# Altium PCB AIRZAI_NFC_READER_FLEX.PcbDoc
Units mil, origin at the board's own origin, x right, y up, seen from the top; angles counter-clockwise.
Board outline 3488.72 x 5808.52 mil, 2 copper layers (Top Layer, Bottom Layer); 39 components, 43 nets, 190 pads, 9 vias.
Unrouted connection lines stored in the file: 129.
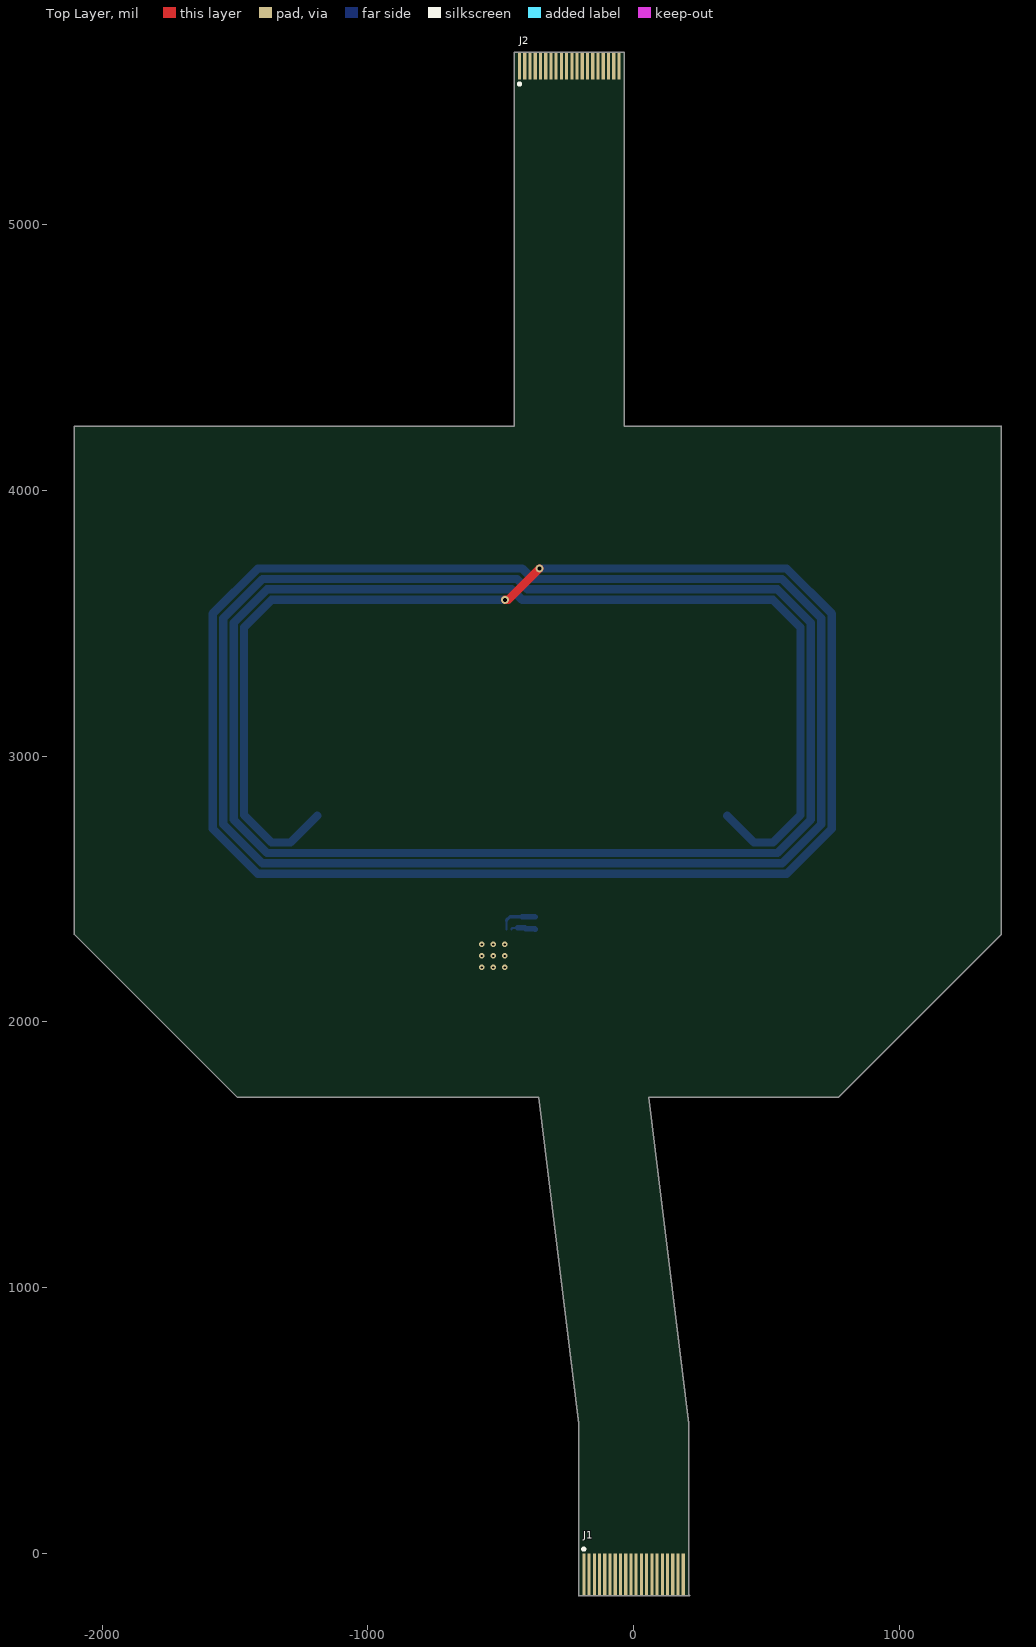
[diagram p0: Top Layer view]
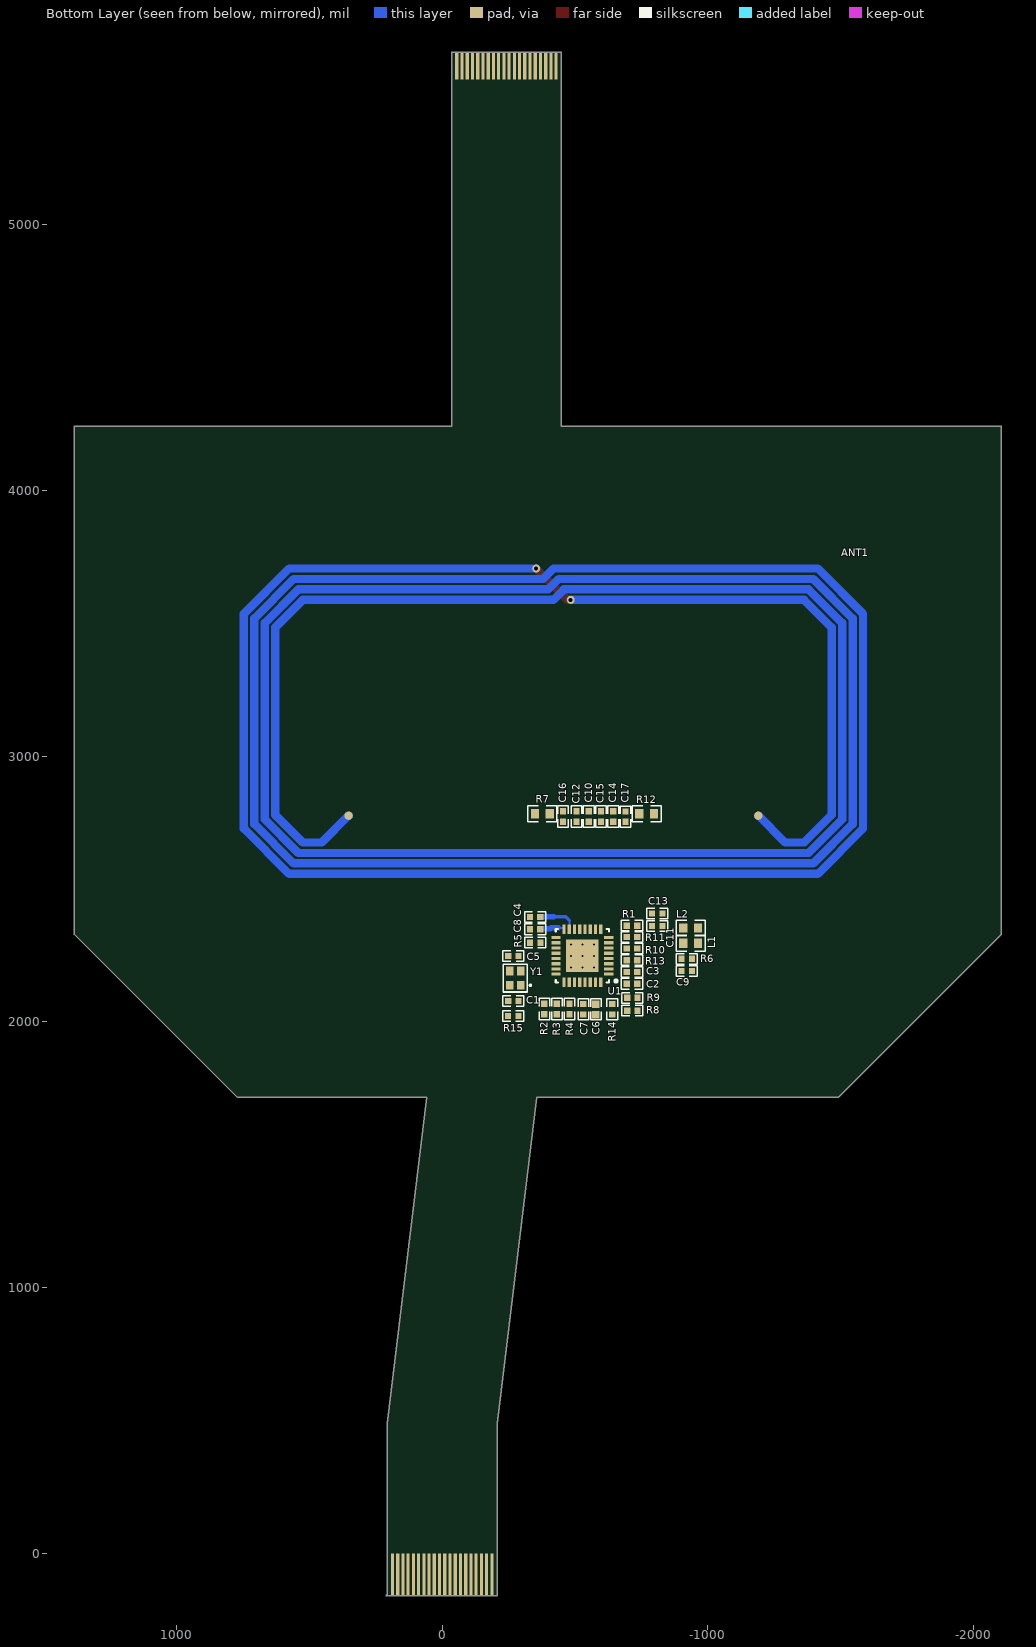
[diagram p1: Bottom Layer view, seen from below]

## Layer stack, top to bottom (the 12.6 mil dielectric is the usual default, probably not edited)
Top Solder: solder mask 0.4, Solder Resist, Dk 3.5
Top Layer: signal copper 1.4
Dielectric 1: dielectric 12.6, FR-4, Dk 4.8
Bottom Layer: signal copper 1.4
Bottom Solder: solder mask 0.4, Solder Resist, Dk 3.5

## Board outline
-1490.79,1715.7 -356.15,1715.7 -206.96,488.48 -206.96,488.46 -206.96,488.48 -206.96,-159.02 ccw(c-206.69,-159.02) -206.69,-159.28 210.63,-159.28 ccw(c210.63,-159.02) 210.89,-159.02 ccw(c210.63,-159.02) 210.63,-158.75 206.96,-158.75 206.96,488.49 ccw(c206.69,488.49) 206.96,488.53 57.77,1715.7 770.31,1715.7 ccw(c770.31,1715.96) 770.5,1715.77 1384.05,2329.32 ccw(c1383.86,2329.5) 1384.12,2329.5 1384.12,2490.96 1384.12,4242.28 ccw(c1383.86,4242.28) 1383.86,4242.55 -35.17,4242.55 -35.17,5648.98 ccw(c-35.43,5648.98) -35.43,5649.24 -448.82,5649.24 ccw(c-448.82,5648.98) -449.08,5648.98 -449.08,4242.55 -2104.33,4242.55 ccw(c-2104.33,4242.28) -2104.6,4242.28 -2104.6,2490.96 -2104.6,2329.5 ccw(c-2104.33,2329.5) -2104.52,2329.32 -1490.97,1715.77 ccw(c-1490.79,1715.96)

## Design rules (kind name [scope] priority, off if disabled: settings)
Clearance Clearance_polygon_5V [OnLayer('Keep-Out Layer') vs (InNet('+5V') AND InPolygon)] p1: gap=10 ignorepadtopadclearanceinfootprint=FALSE
Clearance Clearance_POLYGON_KEEPOUT [(OnLayer('Keep-Out Layer')) vs (InNet('GND') AND InPolygon)] p2: gap=10 ignorepadtopadclearanceinfootprint=FALSE
Clearance [All] p3: gap=6 ignorepadtopadclearanceinfootprint=FALSE
MinimumSolderMaskSliver [All] p1: minsoldermaskwidth=1
PolygonConnect [All] p1: connectstyle=Direct reliefconductorwidth=10 reliefentries=4 polygonreliefangle="90 Angle" airgapwidth=10
RoomDefinition AIRZAI_NFC_READER_FLEX [InComponentClass('AIRZAI_NFC_READER_FLEX')] p1: confinementstyle=ConfineIn formatcopy=TRUE lockcomponents=FALSE outline -17244.57,-12935.21 -2584.57,-12935.21 -2584.57,-3335.21 -17244.57,-3335.21
RoutingVias [All] p1: holewidth=28 width=50 viastyle="Through Hole" minholewidth=8 minwidth=16 maxholewidth=28 maxwidth=50
SilkToSilkClearance [All] p1: silktosilkclearance=1
SilkToSolderMaskClearance [IsPad] p1: minsilkscreentomaskgap=2 clearancetoexposedcopper=TRUE
SolderMaskExpansion [All] p1: expansion=4
UnRoutedNet [All] p1: checkbadconnections=TRUE
Width [All] p1: maxlimit=100 minlimit=6 preferedwidth=10
26 further rules are at their usual default settings.

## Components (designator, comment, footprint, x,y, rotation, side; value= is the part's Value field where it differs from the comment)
ANT1 "NFC_ANT" ANTENNA-NFC-60MMX30MM -419,3132 r0 bottom
C1 "12pF" 0402CAP -267.98,2078.44 r180 bottom
C2 "0.1µF" 0402CAP -714.98,2143.57 r180 bottom
C3 "0.1µF" 0402CAP -714.98,2188.25 r180 bottom
C4 "0.1µF" 0402CAP -349.98,2394.76 r0 bottom
C5 "12pF" 0402CAP -267.98,2248.44 r0 bottom
C6 "1uF" CAPC0402(1005)60_M -578.42,2047.44 r90 bottom
C7 "0.1µF" 0402CAP -531.42,2047.44 r270 bottom
C8 "0.1µF" 0402CAP -349.98,2348.76 r0 bottom
C9 "1nF" 0402CAP -920.37,2191.44 r0 bottom
C10 "18pF" 0402CAP -552,2773 r270 bottom
C11 "220pF" 0402CAP -809.29,2361.22 r180 bottom
C12 "47pF" 0402CAP -506,2773 r90 bottom
C13 "220pF" 0402CAP -809.29,2408.22 r0 bottom
C14 "47pF" 0402CAP -644,2773 r270 bottom
C15 "18pF" 0402CAP -598,2773 r270 bottom
C16 "DNP" 0402CAP -454.44,2773 r90 bottom
C17 "DNP" 0402CAP -690,2772.69 r270 bottom
J1 "FFC Cable" FFC_PADS_MBD -9.84,-80.28 r180 top
J2 "FFC Cable" FFC_PADS_LID -251.97,5597.8 r180 top
L1 "560nH" 0603CAP -935.37,2295.44 r0 bottom
L2 "560mH" 0603CAP -935.37,2353.44 r0 bottom
R1 "0R" 0402 -714.79,2362.44 r180 bottom
R2 "10K" 0402 -384.68,2048.44 r90 bottom
R3 "10K" 0402 -431.68,2048.44 r90 bottom
R4 "10K" 0402 -479.42,2048.44 r90 bottom
R5 "1K" 0402 -350.23,2298.44 r180 bottom
R6 "2.7K" 0402 -920.69,2237.44 r180 bottom
R7 "3.3" 0603 -377,2783 r180 bottom
R8 "10K" 0402 -715.98,2042.44 r180 bottom
R9 "10K" 0402 -715.98,2090.44 r180 bottom
R10 "0R" 0402 -714.98,2276.44 r180 bottom
R11 "0R" 0402 -714.79,2319.44 r180 bottom
R12 "3.3" 0603 -770,2783 r0 bottom
R13 "10K" 0402 -714.79,2232.44 r180 bottom
R14 "0R" 0402 -640.42,2047.44 r270 bottom
R15 "0R" 0402 -267.31,2022.44 r0 bottom
U1 "MFRC52202HN1,115" VFQFN-32-MFRC52202HN1,157 -527.98,2248.76 r0 bottom
Y1 "27.12MHz" XTAL_2016 -274.98,2164.44 r90 bottom

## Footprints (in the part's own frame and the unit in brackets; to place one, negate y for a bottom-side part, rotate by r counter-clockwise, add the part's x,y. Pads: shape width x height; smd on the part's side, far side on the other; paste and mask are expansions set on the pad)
0402 [mm] "Chip Resistor, Body 1.1x0.5mm, IPC High Density"
  rect 0.6x0.6 smd: 1(-0.5,0) 2(0.5,0)
  silkscreen extent -1.02,-0.51 1.02,0.51, body extent -0.5,-0.25 0.5,0.25, height 0.27
0402CAP [mm] "Chip Capacitor, Body 1.1x0.5mm, IPC High Density"
  rect 0.6x0.6 smd: 1(-0.5,0) 2(0.5,0)
  silkscreen extent -1.02,-0.51 1.02,0.51, body extent -0.5,-0.3 0.5,0.3, height 0.19
0603 [mm] "Chip Resistor, Body 1.6x0.8mm, IPC High Density"
  rect 0.8x0.9 smd: 1(-0.7,0) 2(0.7,0)
  silkscreen extent -1.4,-0.76 1.4,0.76, body extent -0.8,-0.41 0.8,0.4, height 0.37
0603CAP [mm] "Chip Capacitor, Body 1.6x0.8mm, IPC High Density"
  rect 0.8x0.9 smd: 1(-0.7,0) 2(0.7,0)
  silkscreen extent -1.4,-0.76 1.4,0.76, body extent -0.8,-0.4 0.8,0.4, height 0.29
ANTENNA-NFC-60MMX30MM [mil] "ANTENNA-ID2+10P-01"
  round 31.5 smd paste-31.5: 1(-771.2,355.65) 2(771.2,355.65)
  round 30 hole 15: 1(-65,-456.69) 2(65,-574.8)
  Top Layer lines w31.5: -771.2,355.65 -872.24,456.69 -943.7,456.69 -1047.24,353.15 -1047.24,-353.15 -943.7,-456.69 -65,-456.69 ; 65,-574.8 994.96,-574.8 1165.35,-404.41 1165.35,404.41 994.96,574.8 -994.96,574.8 -1165.35,404.41 -1165.35,-404.41 -994.96,-574.8 0,-574.8 39.37,-535.43 977.87,-535.43 1125.98,-387.32 1125.98,387.32 977.87,535.43 -977.87,535.43 -1125.98,387.32 -1125.98,-387.32 -977.87,-535.43 -19.37,-535.43 20,-496.06 960.79,-496.06 1086.61,-370.24 1086.61,370.24 960.79,496.06 -960.79,496.06 -1086.61,370.24 -1086.61,-370.24 -960.79,-496.06 -39.37,-496.06 0,-456.69 943.7,-456.69 1047.24,-353.15 1047.24,353.15 943.7,456.69 872.24,456.69 771.2,355.65
  Bottom Layer lines w31.5: -65,-456.69 -53.11,-456.69 65,-574.8
CAPC0402(1005)60_M [mm] "Chip Capacitor, Body 1.0x0.5mm, Height 0.6mm, IPC Low Density"
  rect 0.72x0.72 smd: 1(-0.5,0) 2(0.5,0)
  silkscreen extent -1.02,-0.51 1.02,0.51, body extent -0.55,-0.3 0.55,0.3, height 0.6
FFC_PADS_LID [mm] "(0.50mm"
  rect 0.3x2.6 smd: 1(4.5,0) 2(4,0) 3(3.5,0) 4(3,0) 5(2.5,0) 6(2,0) 7(1.5,0) 8(1,0) 9(0.5,0) 10(0,0) 11(-0.5,0) 12(-1,0) 13(-1.5,0) 14(-2,0) 15(-2.5,0) 16(-3,0) 17(-3.5,0) 18(-4,0) 19(-4.5,0) 20(-5,0)
  rect 0.3x2.6 smd far side: 1(4.5,0) 2(4,0) 3(3.5,0) 4(3,0) 5(2.5,0) 6(2,0) 7(1.5,0) 8(1,0) 9(0.5,0) 10(0,0) 11(-0.5,0) 12(-1,0) 13(-1.5,0) 14(-2,0) 15(-2.5,0) 16(-3,0) 17(-3.5,0) 18(-4,0) 19(-4.5,0) 20(-5,0)
  silkscreen extent 4.37,1.58 4.62,1.83
FFC_PADS_MBD [mm] "(0.50mm"
  rect 0.3x4 smd: 1(4.5,0) 2(4,0) 3(3.5,0) 4(3,0) 5(2.5,0) 6(2,0) 7(1.5,0) 8(1,0) 9(0.5,0) 10(0,0) 11(-0.5,0) 12(-1,0) 13(-1.5,0) 14(-2,0) 15(-2.5,0) 16(-3,0) 17(-3.5,0) 18(-4,0) 19(-4.5,0) 20(-5,0)
  rect 0.3x4 smd far side: 1(4.5,0) 2(4,0) 3(3.5,0) 4(3,0) 5(2.5,0) 6(2,0) 7(1.5,0) 8(1,0) 9(0.5,0) 10(0,0) 11(-0.5,0) 12(-1,0) 13(-1.5,0) 14(-2,0) 15(-2.5,0) 16(-3,0) 17(-3.5,0) 18(-4,0) 19(-4.5,0) 20(-5,0)
  silkscreen extent 4.39,-2.56 4.64,-2.31
VFQFN-32-MFRC52202HN1,157 [mm]
  rect 0.9x0.31 smd: 1(-2.529,1.75) 2(-2.529,1.25) 3(-2.529,0.75) 4(-2.529,0.25) 5(-2.529,-0.25) 6(-2.529,-0.75) 7(-2.529,-1.25) 8(-2.529,-1.75) 17(2.529,-1.75) 18(2.529,-1.25) 19(2.529,-0.75) 20(2.529,-0.25) 21(2.529,0.25) 22(2.529,0.75) 23(2.529,1.25) 24(2.529,1.75)
  rect 0.31x0.9 smd: 9(-1.75,-2.529) 10(-1.25,-2.529) 11(-0.75,-2.529) 12(-0.25,-2.529) 13(0.25,-2.529) 14(0.75,-2.529) 15(1.25,-2.529) 16(1.75,-2.529) 25(1.75,2.529) 26(1.25,2.529) 27(0.75,2.529) 28(0.25,2.529) 29(-0.25,2.529) 30(-0.75,2.529) 31(-1.25,2.529) 32(-1.75,2.529)
  rect 3.1x3.1 smd: 33(0,0)
  silkscreen extent -3.32,-2.55 2.55,2.55, body extent -2.55,-2.55 2.55,2.55, height 1
XTAL_2016 [mm] "2.00mm x 1.60mm"
  rect 0.85x0.75 smd: 1(-0.675,-0.525) 2(0.675,-0.525) 3(0.675,0.525) 4(-0.675,0.525)
  silkscreen extent -1.32,-1.47 1.32,1.14, body extent -1,-0.81 1,0.79, height 0.65

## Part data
C1 C5: library part CAP, "CAP CER 12PF 50V C0G/NP0 0402", Case/Package=0402, Case Code (Metric)=1005, Dielectric=C0G, Dielectric Material=Ceramic, Manufacturer=KEMET, Manufacturer Part Number=C0402C120J5GACTU, Max Operating Temperature=125°C, Min Operating Temperature=-55°C, Package Quantity=1, Supplier Part Number 1=399-1013-6-ND, Temperature Coefficient=30ppm/°C, Tolerance=5%, Voltage=50V
C2 C3 C4 C7 C8: library part C0402-100n, "Capacitor, X7R, ±10%", Case-EIA=0402, Case-Metric=1005, Manufacturer=TDK, Manufacturer Part Number=C1005X7R1C104K, Rated Voltage="16 V", Supplier Part Number 1=445-4952-2-ND, Tolerance=±20%
C6: library part CAP, "CAP 1uF 16V ±10% 0402 (1005 Metric) Thickness 0.6mm SMD", Case/Package=0402, Case Code (Metric)=1005, Dielectric=X5R, Manufacturer="Taiyo Yuden", Manufacturer Part Number=EMK105BJ105KV-F, Max Operating Temperature=85°C, Min Operating Temperature=-55°C, Package Quantity=1, Supplier Part Number 1=587-2477-6-ND, Tolerance=10%, Voltage Rating=16V
C9: library part 56p, "CAP CER 1000PF 50V C0G/NP0 0402", Case/Package=0402, Case Code (Metric)=1005, Dielectric=C0G, Manufacturer=Murata, Manufacturer Part Number=GRM1555C1H102FA01D, Max Operating Temperature=125°C, Min Operating Temperature=-55°C, Package Quantity=1, Supplier Part Number 1=490-6189-1-ND, Tolerance=1%, Voltage=50V
C10 C15: library part 56p, "CAP CER 18PF 50V NP0 0402", Case/Package=0402, Case Code (Metric)=1005, Dielectric=C0G, Manufacturer="Kyocera AVX", Manufacturer Part Number=04025U180FAT2A, Max Operating Temperature=125°C, Min Operating Temperature=-55°C, Package Quantity=10000, Supplier Part Number 1=478-10144-1-ND, Tolerance=1%, Voltage Rating=50V
C11 C13: library part 56p, "CAP CER 220PF 50V NPO 0402", Case/Package=0402, Case Code (Metric)=1005, Dielectric=C0G, Manufacturer=Yageo, Manufacturer Part Number=CC0402FRNPO9BN221, Max Operating Temperature=125°C, Min Operating Temperature=-55°C, Supplier Part Number 1=311-3730-1-ND, Tolerance=1%, Voltage Rating=50V
C12 C14: library part 56p, "CAP CER 47PF 50V C0G/NP0 0402", Dielectric=C0G, Manufacturer=Murata, Manufacturer Part Number=GJM1555C1H470FB01D, Supplier Part Number 1=490-16376-1-ND, Tolerance=1%, Voltage Rating (DC)=50V
C16 C17: library part 56p
J1 J2: library part XF2M-2015-1A-R100, "Cable"
L1: library part Inductor, "FIXED IND 560NH 100MA 1.05 OHM", Case/Package=0603, Case Code (Metric)=1608, Current Rating=100mA, DC Resistance (DCR)=1.05R, Manufacturer=TDK, Manufacturer Part Number=MLF1608DR56JTD25, Max DC Current=30mA, Max Operating Temperature=125°C, Min Operating Temperature=-55°C, Package Quantity=4000, Ratings=AEC-Q200, Self Resonant Frequency=170MHz, Supplier Part Number 1=445-16970-1-ND, Test Frequency=25MHz, Tolerance=5%
L2: library part Inductor, "FIXED IND 560NH 100MA 1.05 OHM", Case/Package=0603, Case Code (Metric)=1608, Current Rating=100mA, DC Resistance (DCR)=1.05R, Inductance=560nH, Manufacturer=TDK, Manufacturer Part Number=MLF1608DR56JTD25, Max DC Current=30mA, Max Operating Temperature=125°C, Min Operating Temperature=-55°C, Package Quantity=4000, Ratings=AEC-Q200, Self Resonant Frequency=170MHz, Supplier Part Number 1=445-16970-1-ND, Test Frequency=25MHz, Tolerance=5%
R1 R10 R11 R14 R15: library part R0402-12k, "Resistor, ±1%, 0.063W", Case-EIA=0402, Case-Metric=1005, Manufacturer=Panasonic, Manufacturer Part Number=ERJ-2GE0R00X, Supplier Part Number 1=P0.0JTR-ND, Tolerance=±5%
R2 R3 R4 R8 R9 R13: library part R0402-12k, "Resistor 10K, ±1%, 0.063W", Case/Package=0402, Case Code (Metric)=1005, Manufacturer="Vishay Dale", Manufacturer Part Number=CRCW040210K0JNED, Max Operating Temperature=155°C, Max Power Dissipation=63mW, Min Operating Temperature=-55°C, Package Quantity=1, Resistance=10kR, Supplier Part Number 1=541-10KJDKR-ND, Temperature Coefficient=200ppm/°C, Tolerance=5%, Voltage Rating=50V
R5: library part R0402-12k, "RES SMD 1K OHM 1% 1/16W 0402", Case/Package=0402, Case Code (Metric)=1005, Manufacturer=Yageo, Manufacturer Part Number=RC0402FR-071KL, Max Operating Temperature=155°C, Min Operating Temperature=-55°C, Power Rating=62.5mW, Resistance=1kR, Supplier Part Number 1=311-1.00KLRCT-ND, Temperature Coefficient=100ppm/°C, Tolerance=1%, Voltage Rating=50V
R6: library part R0402-12k, "RES SMD 2.7K OHM 1% 1/16W 0402", Case/Package=0402, Manufacturer="Yageo Phycomp", Manufacturer Part Number=RC0402FR-072K7L, Max Operating Temperature=155°C, Min Operating Temperature=-55°C, Power Rating=63mW, Resistance=2.7kR, Supplier Part Number 1=311-2.70KLRCT-ND, Temperature Coefficient=100ppm/°C, Tolerance=1%, Voltage Rating (DC)=50V
R7 R12: library part R0402-12k, "RES SMD 3.3 OHM 1% 1/10W 0603", Case/Package=0603, Manufacturer=Yageo, Manufacturer Part Number=AC0603FR-073R3L, Max Operating Temperature=155°C, Max Power Dissipation=100mW, Min Operating Temperature=-55°C, Resistance=3.3R, Supplier Part Number 1=YAG5335CT-ND, Temperature Coefficient=200ppm/°C, Tolerance=1%
U1: library part MFRC52201HN1,157, "IC RFID READER 13.56MHZ 32HVQFN", Frequency=13.56MHz, Manufacturer="NXP Semiconductors", Max Operating Temperature=85°C, Min Operating Temperature=-25°C, Package Quantity=1500, Supplier Part Number 1=568-15200-1-ND
Y1: library part ZTB_2, "CRYSTAL 27.12MHZ 10PF SMD", Manufacturer="ECS International", Manufacturer Part Number=ECS-271.2-10-37-CKM-TR, Supplier Part Number 1=XC2511DKR-ND

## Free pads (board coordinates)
  round 31.5 on Mech4: 3(0,0)

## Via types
v1: diameter 19.68, hole 8, Top Layer to Bottom Layer, 9 vias

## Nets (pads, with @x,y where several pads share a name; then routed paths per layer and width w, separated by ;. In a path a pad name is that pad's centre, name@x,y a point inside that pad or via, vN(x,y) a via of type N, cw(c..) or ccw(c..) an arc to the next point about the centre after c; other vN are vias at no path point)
3V3: C2.1 C3.1 C4.1 C6.2 C7.1 J1.18 J2.18 R1.2 R9.2 R13.2 U1.2 U1.3 U1.12 U1.15 | length 149.2
  Bottom Layer w8: U1.15 -478.77,2380
  Bottom Layer w12: -478.77,2380 -478.77,2382.23 -465,2396 -420,2396
  Bottom Layer w20: -420,2396 -370.91,2396 C4.1
+5: J1.19 J1.20 J2.19 J2.20
ACCELERO_INT: J1.14 J2.14
ADC_CH1: J1.5 J2.5
CAP1_TOUCH_OUT: J1.7 J2.7
CAP2_TOUCH_OUT: J1.8 J2.8
EN: J1.17 J2.17
GND: C1.1 C2.2 C3.2 C4.2 C5.1 C6.1 C7.2 C8.2 C11.1 C12.1 C13.2 C14.2 C16.1 C17.2 J1.1 J1.2 J2.1 J2.2 R2.1 R3.1 R4.1 R8.2 R10.2 R11.2 U1.4 U1.5 U1.10 U1.14 U1.18 U1.33 Y1.2 Y1.4
  other v1: -571.29,2205.45 -527.98,2205.45 -484.67,2205.45 -571.29,2248.76 -527.98,2248.76 -484.67,2248.76 -571.29,2292.07 -527.98,2292.07 -484.67,2292.07
"LED Str CLK": J1.10 J2.10
"LED Str DATA": J1.11 J2.11
NetANT1_1: ANT1.1 R7.1
NetANT1_2: ANT1.2 R12.1
NetC1_2: C1.2 U1.21 Y1.3
NetC5_2: C5.2 U1.22 Y1.1
NetC9_1: C9.1 R6.2
NetC9_2: C9.2 R5.2 U1.17
NetC10_1: C10.1 C12.2 C16.2 R7.2
NetC10_2: C10.2 C11.2 L1.2 R6.1
NetC13_1: C13.1 C15.2 L2.2
NetC14_1: C14.1 C15.1 C17.1 R12.2
NetL1_1: L1.1 U1.11
NetL2_1: L2.1 U1.13
NetR1_1: R1.1 U1.9
NetR2_2: R2.2 U1.28
NetR3_2: R3.2 U1.29
NetR4_2: R4.2 U1.30
NetR8_1: R8.1 U1.32
NetR9_1: R9.1 U1.1
NetR10_1: R10.1 U1.7
NetR11_1: R11.1 U1.8
NetR13_1: R13.1 U1.6
NetR14_1: R14.1 U1.31
NetR15_1: R15.1 U1.24
NetTP2_1: U1.23
NFC_INT: J1.12 J2.12
PWM1: J1.4 J2.4
PWM2: J1.3 J2.3
SCL: J1.15 J2.15 R14.2
SDA: J1.16 J2.16 R15.2
SPR_GPO1: J1.9 J2.9
SPR_GPO2: J1.6 J2.6
TOFINT: J1.13 J2.13
VMID: C8.1 R5.1 U1.16 | length 96
  Bottom Layer w8: U1.16 -459.08,2351.9 -456.98,2354 -437,2354
  Bottom Layer w20: -437,2354 -410,2354 -406.57,2350.57 -371.48,2350.57 C8.1
pads on no net: U1.19 U1.20 U1.25 U1.26 U1.27

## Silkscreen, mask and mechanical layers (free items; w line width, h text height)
Mechanical 1:
  drawing of 4184 lines, arcs and shapes, not listed
  text "6" at -8464.44,8776.65 h121.11
  text "5" at -4921.14,8776.65 h121.11
  text "4" at -1377.83,8776.65 h121.11
  text "3" at 2165.48,8776.65 h121.11
  text "2" at 5708.78,8776.65 h121.11
  text "1" at 9252.09,8776.65 h121.11
  text "APPD/DATE" at 10754.91,8441.56 h80.74
  text "ZONE" at 5296.69,8438.99 h80.74
  text "ECN" at 4408.53,8435.96 h80.74
  text "ISSUE" at 4852.61,8435.96 h80.74
  text "DESCRIPTION" at 7330.77,8435.96 h80.74
  text "DRN/DATE" at 9537.92,8435.96 h80.74
  text "CHK/DATE" at 10150.79,8435.96 h80.74
  text "NOTE: THIS DRAWING WAS PRODUCED BY COMPUTER, DO NOT UPDATE MANUALLY" at -10037.66,8286.98 h157.48
  text "E" at -10370.77,7099.24 h121.11
  text "E" at 11234.86,7099.24 h121.11
  text "9,35" at 4637.3,5563 h137.8
  text "R0,4" at -5063.14,5245.14 h137.8 r322.13
  text "R0,4" at -4833.65,5219.74 h137.8 r28.27
  text "R0,4" at -5293.76,5059.77 h137.8 r49.62
  text "1,9" at 5922.79,4874.54 h137.8 r90
  text "18,3" at 6531.82,4714.87 h137.8 r90
  text "R0,4" at -4583.06,4495.32 h137.8 r346.55
  text "R1,5" at -4668.58,4198.63 h137.8 r297.71
  text "5,7" at 4680.26,4169.16 h137.8
  text "D" at -10370.77,4107.12 h121.11
  text "D" at 11234.86,4107.12 h121.11
  text "10,6" at 342.6,3949.32 h137.8
  text "42,2" at 6530.95,3523.98 h137.8 r90
  text "3,2" at 5054.45,3068.36 h137.8
  text "R1,5" at -4911.86,3031.88 h137.8 r52.37
  text "R1,7" at -4816.39,2845.06 h137.8 r19.46
  text "56" at 6523.19,1590.92 h137.8 r90
  text "C" at -10382.31,1114.99 h121.11
  text "C" at 11234.86,1114.99 h121.11
  text "~}" at -857.14,1063.03 h137.8
  text "R1,7" at -4693.44,641.91 h137.8 r337.84
  text "R1,7" at -4912.79,634.79 h137.8 r324.73
  text "3,2" at 4816.59,510.89 h137.8
  text "R0,4" at -4832.73,370.26 h137.8 r323.84
  text "2" at 4902.35,-62.45 h137.8
  text "6" at 6521.11,-67.84 h137.8 r90
  text "B" at -10370.77,-1877.14 h121.11
  text "B" at 11234.86,-1877.14 h121.11
  text "Coremi Industries Co., Limited" at 6560.31,-4696.46 h196.85
  text "T10" at 10490.36,-4844.78 h137.8
  text "A" at -10405.38,-4869.26 h121.11
  text "A" at 11234.86,-4869.26 h121.11
  text "REVISION NO." at 9505.71,-4883.53 h99.5
  text "DRAWING NO." at 6558.31,-4950.46 h99.5
  text "Airzai-041T10" at 7802.31,-4973.46 h137.8
  text "Airzai" at 9680.39,-5035.58 h137.8
  text "MODEL :" at 9033.27,-5119.75 h99.5
  text "MANIFOLD_SOLID_BREP_27740" at 7108.31,-5163.46 h98.43
  text "TITLE:" at 6544.31,-5165.46 h99.5
  text "METERIAL:" at 6552.95,-5355.97 h99.5
  text "MASS :                 kg" at 9033.27,-5355.97 h99.5
  text "1" at 8307.08,-5554.58 h137.8
  text "P/N:" at 9033.27,-5582.88 h118.11
  text "FINISH:" at 6552.95,-5592.19 h99.5
  text "QTY:" at 7832.48,-5592.19 h99.5
  text "NOTE:" at -9495.13,-5675.71 h118.11
  text ".  TOLERANCES  ." at 7801.65,-5756.65 h79.6
  text "1:1" at 7084.98,-5782.28 h137.8
  text "1.UNSPECIFIED DRAFT ANGLE 1.0\Fgdt;{\Fgdt;~}" at -9495.13,-5795 h118.11
  text "SCALE:" at 6552.95,-5828.41 h99.5
  text "DRN.DATE" at 9033.27,-5828.41 h99.5
  text "Daniel Apr/20,2019" at 9686.72,-5852.35 h118.11
  text "All dimensions are in mm" at 7795.28,-5887.71 h59.7
  text "\Ftxt;2.UNSPECIFIED FILLET TO BE R0.3" at -9495.13,-5914.29 h118.11
  text "Daniel Apr/20,201" at 9686.72,-5971.64 h118.11
  text "unless otherwise specified." at 7804.84,-5996.08 h59.7
  text "A2" at -10123.77,-6059.89 h236.22
  text "PROJECTION" at 6552.95,-6064.63 h99.5
  text "CHK.DATE" at 9033.27,-6064.63 h99.5
  text "X" at 8097.09,-6092.43 h59.7
  text "0.20" at 8504.19,-6092.43 h59.7
  text ".X" at 8097.09,-6179.24 h59.7
  text "0.10" at 8504.19,-6179.24 h59.7
  text ".XX" at 8097.09,-6266.05 h59.7
  text "0.05" at 8504.19,-6266.05 h59.7
  text "1  1" at 7070.84,-6290.34 h137.8
  text "SHEET   OF" at 6552.95,-6300.85 h99.5
  text "APP.DATE" at 9033.27,-6300.85 h99.5
  text "ANGLE" at 8081.75,-6352.86 h59.7
  text "~}" at 8504.19,-6352.86 h59.7
  text "6" at -8464.44,-6576.72 h121.11
  text "5" at -4921.14,-6576.72 h121.11
  text "4" at -1377.83,-6576.72 h121.11
  text "3" at 2165.48,-6576.72 h121.11
  text "2" at 5708.78,-6576.72 h121.11
  text "1" at 9252.09,-6576.72 h121.11
Mechanical 2:
  lines w0.5: 7342.3,-6090.57 7525.03,-6090.57 ; 7433.66,-6181.94 7433.66,-5999.2 ; 7484.22,-6091.22 7772.02,-6091.22
Mechanical 4:
  lines w0.5: 206.69,-159.02 206.69,488.49 57.47,1715.96 770.31,1715.96 1383.86,2329.5 1383.86,2490.96 1383.86,4242.28 -35.43,4242.28 -35.43,5648.98 -448.82,5648.98 -448.82,4242.28 -2104.33,4242.28 -2104.33,2490.96 -2104.33,2329.5 -1490.79,1715.96 -355.91,1715.96 -206.69,488.49 -206.69,-159.02 210.63,-159.02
